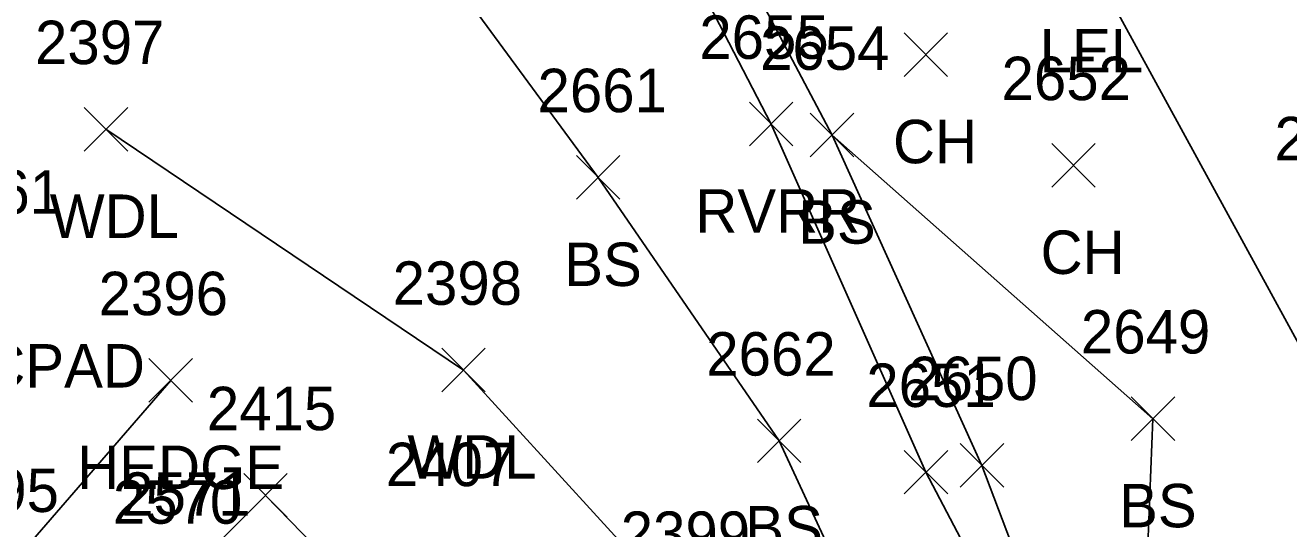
# Model space of a CAD drawing. Extents: x 1653135 to 1655489, y 602711 to 605684.
# Drawn here: x 1653689.3 to 1653747.4, y 605301.7 to 605324.9 of the extents above; entities that cross this region are included whole.
import ezdxf

# ---------------------------------------------------------------- set-up
doc = ezdxf.new("R2010")
doc.units = 0
for name, color, linetype in [('L_A', 7, 'Continuous'), ('L_I', 7, 'Continuous'), ('L_TIC', 7, 'Continuous'), ('LAHR', 7, 'Continuous'), ('LARO', 7, 'Continuous'), ('LAWA', 7, 'Continuous'), ('LAWE', 7, 'Continuous'), ('LBC', 7, 'Continuous'), ('LELB', 7, 'Continuous'), ('R_I', 7, 'Continuous'), ('U_I', 7, 'Continuous')]:
    doc.layers.add(name, color=color, linetype=linetype)

msp = doc.modelspace()

# ---------------------------------------------------------------- linework, layer by layer
at = {"layer": 'L_TIC'}
for points in [[(1653729.68, 605322.51), (1653731.68, 605324.51)], [(1653731.68, 605322.51), (1653729.68, 605324.51)], [(1653729.68, 605322.51), (1653731.68, 605324.51)], [(1653731.68, 605322.51), (1653729.68, 605324.51)], [(1653691.976, 605319.073), (1653693.976, 605321.073)], [(1653693.976, 605319.073), (1653691.976, 605321.073)], [(1653691.976, 605319.073), (1653693.976, 605321.073)], [(1653693.976, 605319.073), (1653691.976, 605321.073)], [(1653722.568, 605319.315), (1653724.568, 605321.315)], [(1653724.568, 605319.315), (1653722.568, 605321.315)], [(1653722.568, 605319.315), (1653724.568, 605321.315)], [(1653724.568, 605319.315), (1653722.568, 605321.315)], [(1653725.363, 605318.809), (1653727.363, 605320.809)], [(1653727.363, 605318.809), (1653725.363, 605320.809)], [(1653725.363, 605318.809), (1653727.363, 605320.809)], [(1653727.363, 605318.809), (1653725.363, 605320.809)], [(1653725.363, 605318.809), (1653727.363, 605320.809)], [(1653727.363, 605318.809), (1653725.363, 605320.809)], [(1653725.363, 605318.809), (1653727.363, 605320.809)], [(1653727.363, 605318.809), (1653725.363, 605320.809)], [(1653736.465, 605317.415), (1653738.465, 605319.415)], [(1653738.465, 605317.415), (1653736.465, 605319.415)], [(1653736.465, 605317.415), (1653738.465, 605319.415)], [(1653738.465, 605317.415), (1653736.465, 605319.415)], [(1653714.609, 605316.861), (1653716.609, 605318.861)], [(1653716.609, 605316.861), (1653714.609, 605318.861)], [(1653714.609, 605316.861), (1653716.609, 605318.861)], [(1653716.609, 605316.861), (1653714.609, 605318.861)], [(1653708.42, 605307.994), (1653710.42, 605309.994)], [(1653710.42, 605307.994), (1653708.42, 605309.994)], [(1653708.42, 605307.994), (1653710.42, 605309.994)], [(1653710.42, 605307.994), (1653708.42, 605309.994)], [(1653694.956, 605307.517), (1653696.956, 605309.517)], [(1653696.956, 605307.517), (1653694.956, 605309.517)], [(1653694.956, 605307.517), (1653696.956, 605309.517)], [(1653696.956, 605307.517), (1653694.956, 605309.517)], [(1653740.122, 605305.754), (1653742.122, 605307.754)], [(1653742.122, 605305.754), (1653740.122, 605307.754)], [(1653740.122, 605305.754), (1653742.122, 605307.754)], [(1653742.122, 605305.754), (1653740.122, 605307.754)], [(1653722.934, 605304.737), (1653724.934, 605306.737)], [(1653724.934, 605304.737), (1653722.934, 605306.737)], [(1653722.934, 605304.737), (1653724.934, 605306.737)], [(1653724.934, 605304.737), (1653722.934, 605306.737)], [(1653729.682, 605303.293), (1653731.682, 605305.293)], [(1653731.682, 605303.293), (1653729.682, 605305.293)], [(1653729.682, 605303.293), (1653731.682, 605305.293)], [(1653731.682, 605303.293), (1653729.682, 605305.293)], [(1653732.259, 605303.606), (1653734.259, 605305.606)], [(1653734.259, 605303.606), (1653732.259, 605305.606)], [(1653732.259, 605303.606), (1653734.259, 605305.606)], [(1653734.259, 605303.606), (1653732.259, 605305.606)], [(1653699.31, 605302.223), (1653701.31, 605304.223)], [(1653701.31, 605302.223), (1653699.31, 605304.223)], [(1653699.31, 605302.223), (1653701.31, 605304.223)], [(1653701.31, 605302.223), (1653699.31, 605304.223)]]:
    msp.add_lwpolyline(points, dxfattribs=at)
at = {"layer": 'LAHR'}
msp.add_lwpolyline([(1653688.126, 605299.458), (1653695.956, 605308.517)], dxfattribs=at)
at = {"layer": 'LARO'}
msp.add_lwpolyline([(1653767.281, 605327.457), (1653769.204, 605314.569), (1653768.725, 605314.583), (1653767.912, 605313.714), (1653756.317, 605320.903), (1653747.283, 605332.192), (1653741.591, 605331.178), (1653738.275, 605327.692), (1653750.788, 605304.76), (1653751.008, 605292.603), (1653744.327, 605283.215)], dxfattribs=at)
at = {"layer": 'LAWA'}
msp.add_lwpolyline([(1653692.976, 605320.073), (1653709.42, 605308.994), (1653719.916, 605297.482), (1653727.245, 605289.031)], dxfattribs=at)
at = {"layer": 'LAWE'}
msp.add_lwpolyline([(1653733.79, 605289.723), (1653736.619, 605292.952), (1653730.682, 605304.293), (1653723.568, 605320.315), (1653713.009, 605340.72)], dxfattribs=at)
at = {"layer": 'LBC'}
for points in [[(1653700.31, 605303.223), (1653707.103, 605296.241), (1653702.404, 605291.53), (1653698.876, 605294.964), (1653699.902, 605295.811), (1653696.643, 605298.919), (1653696.373, 605299.283)], [(1653696.373, 605299.283), (1653700.31, 605303.223)]]:
    msp.add_lwpolyline(points, dxfattribs=at)
at = {"layer": 'LELB'}
for points in [[(1653739.666, 605287.119), (1653740.653, 605295.086), (1653741.122, 605306.754), (1653726.363, 605319.809), (1653714.427, 605342.424)], [(1653702.889, 605335.187), (1653715.609, 605317.861), (1653723.934, 605305.737), (1653728.21, 605296.492), (1653730.413, 605291.325)], [(1653737.231, 605285.328), (1653734.386, 605289.04), (1653737.591, 605293.132), (1653733.259, 605304.606), (1653726.363, 605319.809)]]:
    msp.add_lwpolyline(points, dxfattribs=at)

# ---------------------------------------------------------------- texts
at = {"layer": 'L_A'}
for s, p in [('LEL', (1653735.913, 605322.692)), ('LEL', (1653735.913, 605322.692)), ('CH', (1653729.168, 605318.51)), ('CH', (1653729.168, 605318.51)), ('RVRR', (1653720.08, 605315.315)), ('RVRR', (1653720.08, 605315.315)), ('WDL', (1653690.393, 605315.073)), ('WDL', (1653690.393, 605315.073)), ('BS', (1653724.804, 605314.809)), ('BS', (1653724.804, 605314.809)), ('BS', (1653724.804, 605314.809)), ('BS', (1653724.804, 605314.809)), ('CH', (1653735.953, 605313.415)), ('CH', (1653735.953, 605313.415)), ('BS', (1653714.05, 605312.861)), ('BS', (1653714.05, 605312.861)), ('CONCPAD', (1653681.395, 605308.187)), ('CONCPAD', (1653681.395, 605308.187)), ('CONCPAD', (1653681.395, 605308.187)), ('CONCPAD', (1653681.395, 605308.187)), ('WDL', (1653706.837, 605303.994)), ('WDL', (1653706.837, 605303.994)), ('HEDGE', (1653691.657, 605303.517)), ('HEDGE', (1653691.657, 605303.517)), ('BS', (1653739.563, 605301.754)), ('BS', (1653739.563, 605301.754)), ('BS', (1653722.375, 605300.737)), ('BS', (1653722.375, 605300.737))]:
    msp.add_text(s, height=2, dxfattribs=at).set_placement(p)
at = {"layer": 'L_I'}
for s, p in [('2397', (1653689.716, 605323.073)), ('2397', (1653689.716, 605323.073)), ('2655', (1653720.261, 605323.315)), ('2655', (1653720.261, 605323.315)), ('2654', (1653723.056, 605322.809)), ('2654', (1653723.056, 605322.809)), ('2654', (1653723.056, 605322.809)), ('2654', (1653723.056, 605322.809)), ('2652', (1653734.158, 605321.415)), ('2652', (1653734.158, 605321.415)), ('2661', (1653712.822, 605320.861)), ('2661', (1653712.822, 605320.861)), ('2222', (1653746.712, 605318.648)), ('2222', (1653746.712, 605318.648)), ('4961', (1653685.009, 605316.187)), ('4961', (1653685.009, 605316.187)), ('4961', (1653685.009, 605316.187)), ('4961', (1653685.009, 605316.187)), ('2398', (1653706.16, 605311.994)), ('2398', (1653706.16, 605311.994)), ('2396', (1653692.641, 605311.517)), ('2396', (1653692.641, 605311.517)), ('2649', (1653737.807, 605309.754)), ('2649', (1653737.807, 605309.754)), ('2662', (1653720.58, 605308.737)), ('2662', (1653720.58, 605308.737)), ('2651', (1653727.942, 605307.293)), ('2651', (1653727.942, 605307.293)), ('2650', (1653729.866, 605307.606)), ('2650', (1653729.866, 605307.606)), ('2415', (1653697.617, 605306.223)), ('2415', (1653697.617, 605306.223)), ('2395', (1653684.866, 605302.458)), ('2395', (1653684.866, 605302.458)), ('2570', (1653693.296, 605301.919)), ('2570', (1653693.296, 605301.919)), ('2571', (1653693.681, 605302.283)), ('2571', (1653693.681, 605302.283)), ('2399', (1653716.648, 605300.482)), ('2399', (1653716.648, 605300.482))]:
    msp.add_text(s, height=2, dxfattribs=at).set_placement(p)
at = {"layer": 'R_I'}
msp.add_text('2570', height=2, dxfattribs=at).set_placement((1653693.296, 605301.919))
msp.add_text('2570', height=2, dxfattribs=at).set_placement((1653693.296, 605301.919))
at = {"layer": 'U_I'}
msp.add_text('2407', height=2, dxfattribs=at).set_placement((1653705.848, 605303.649))

doc.saveas('drawing.dxf')
